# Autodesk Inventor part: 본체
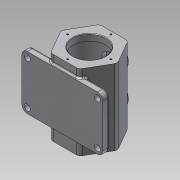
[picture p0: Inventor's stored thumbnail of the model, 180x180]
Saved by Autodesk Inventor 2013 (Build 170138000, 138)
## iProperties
Created: 2021-06
Part Number: 본체
Material: 알루미늄 6061
Document SubType Name: Modeling
Designer: Administrator
Mass: 1500.81 g
Surface Area: 1102.36 cm^2
Volume: 553.806 cm^3
Density: 2.71 g/cm^3
Author: Administrator
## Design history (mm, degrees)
sketch "스케치1" dims "d0" = 105
  geometry: L1 (-52.5, 0)-(-26.25, 45.466); L2 (-26.25, 45.466)-(26.25, 45.466); L3 (26.25, 45.466)-(52.5, 0); L4 (52.5, 0)-(26.25, -45.466); L5 (26.25, -45.466)-(-26.25, -45.466); L6 (-26.25, -45.466)-(-52.5, 0); L7 (-73.5, 0)-(73.5, 0) reference; L8 (0, -73.5)-(0, 73.5) reference; 3 further points
  constraints: 12 end point, 2 coincident, 1 horizontal alignment, 15 other
  dimensions: "d2" = 30 deg angle of L8 L3
extrude "돌출1" new body sketch "스케치1" stored distance "d4" = 140; taper "d5" = 0 deg
sketch "스케치2"
  geometry: C1 r 30 at (0, 0); 1 further point
  constraints: 1 centre point, 1 coincident
  dimensions: "d6" = 60 diameter of C1
extrude "돌출2" cut sketch "스케치2" distance "d8" = 12; taper "d9" = 0 deg
sketch "스케치3"
  geometry: C1 r 30 at (0, 0) reference; C2 r 37.5 at (0, 0)
  constraints: 1 centre point, 1 coincident
  dimensions: "d10" = 75 diameter of C2
extrude "돌출3" cut sketch "스케치3" distance "d12" = 116; taper "d13" = 0 deg
sketch "스케치4"
  geometry: C1 r 30 at (0, 0); 1 further point
  constraints: 1 centre point, 1 coincident
  dimensions: "d14" = 60 diameter of C1
extrude "돌출4" cut sketch "스케치4" distance "d16" = 12; taper "d17" = 0 deg
node "작업 평면1"
sketch "스케치5"
  geometry: L1 (-26.25, 70)-(26.25, 70) reference; C1 r 20 at (0, 30); C2 r 20 at (0, -30); 1 further point
  constraints: 2 centre point, 2 vertical alignment
  dimensions: "d19" = 40 distance from line of L1 C1.centre; "d20" = 60 distance of C2.centre C1.centre; "d21" = 40 diameter of C1; "d22" = 40 diameter of C2
extrude "돌출5" join sketch "스케치5" stored distance "d23" = 8; taper "d24" = 0 deg
sketch "스케치6"
  geometry: C1 r 20 at (0, 0) reference; C2 r 20 at (0, 60) reference; C3 r 15 at (0, 0); C4 r 15 at (0, 60); 1 further point
  constraints: 2 centre point, 2 coincident
  dimensions: "d25" = 30 diameter of C3; "d27" = 30 diameter of C4
extrude "돌출6" cut sketch "스케치6" distance "d28" = 8; taper "d29" = 0 deg
sketch "스케치7"
  geometry: C1 r 15 at (0, 0) reference; C2 r 15 at (0, -60) reference; C3 r 12.5 at (0, 0); C4 r 12.5 at (0, -60); 1 further point
  constraints: 2 centre point, 2 coincident
  dimensions: "d30" = 25 diameter of C3; "d32" = 25 diameter of C4
extrude "돌출7" cut sketch "스케치7" distance "d33" = 20; taper "d34" = 0 deg
sketch "스케치8"
  geometry: C1 r 30 at (0, 0) reference; 1 further point
  constraints: 1 vertical alignment
  dimensions: "d35" = 40 distance of point (0, 40) C1.centre
hole "구멍1" sketch "스케치8" at (0, 40) diameter "d36" = 3.242; stored, may be unused: countersink angle "d40" = 90 deg, drill point angle "d42" = 118 deg; dims "d37" = 8, "d38" = 30, "d39" = 8, "d41" = 10
sketch "스케치9"
  geometry: L1 (0, 0)-(28.284, 28.284); L2 (73.5, 0)-(-73.5, 0) reference; C1 r 30 at (0, 0) reference; 1 further point
  constraints: 2 end point, 1 coincident
  dimensions: "d46" = 40 distance of L1.start L1.end; "d47" = 45 deg angle of L2 L1
hole "구멍2" sketch "스케치9" at (28.284, 28.284) diameter "d48" = 3.242; stored, may be unused: countersink angle "d52" = 90 deg, drill point angle "d54" = 118 deg; dims "d49" = 8, "d50" = 30, "d51" = 8, "d53" = 10
node "작업 평면2"
sketch "스케치10"
  geometry: L1 (-75, 55)-(75, 55); L2 (75, 55)-(75, -45); L3 (75, -45)-(-75, -45); L4 (-75, -45)-(-75, 55); L5 (128.2, 0)-(-139.2, 0) reference; L6 (0, -98)-(0, 98) reference; L7 (52.5, -70)-(26.25, -70) reference; 1 further point
  constraints: 8 end point, 2 parallel, 1 horizontal, 1 perpendicular, 1 other
  dimensions: "d59" = 150 distance between parallel lines of L4 L2; "d61" = 25 distance between parallel lines of L7 L3; "d62" = 100 distance between parallel lines of L3 L1
extrude "돌출8" join sketch "스케치10" distance "d63" = 12; taper "d64" = 0 deg
fillet "모깎기1" dims "d65" = 10
sketch "스케치11"
  geometry: C1 r 5.5 at (-65, 35); C2 r 5.5 at (-65, -45); C3 r 5.5 at (65, -45); C4 r 5.5 at (65, 35); A1 r 10 centre (-65, -45) between (-75, -45) and (-65, -55) reference; A2 r 10 centre (-65, 35) between (-65, 45) and (-75, 35) reference; A3 r 10 centre (65, 35) between (75, 35) and (65, 45) reference; A4 r 10 centre (65, -45) between (65, -55) and (75, -45) reference; 1 further point
  constraints: 4 centre point, 4 coincident
  dimensions: "d66" = 11 diameter of C1; "d68" = 11 diameter of C2; "d69" = 11 diameter of C3; "d70" = 11 diameter of C4
extrude "돌출9" cut sketch "스케치11" distance "d71" = 12; taper "d72" = 0 deg
sketch "스케치12"
  geometry: L1 (75, -45)-(75, 35) reference; L2 (30.561, -55)-(65, -55) reference; 2 further points
  constraints: 1 other
  dimensions: "d73" = 14 distance from line of L1 point (61, -5); "d74" = 50 distance from line of L2 point (61, -5)
feature "엠보싱1" sketch "스케치12" dims "d75" = 0.5, "d76" = 0
fillet "모깎기2" dims "d77" = 8
fillet "모깎기3" dims "d78" = 5
fillet "모깎기4" dims "d79" = 3
chamfer "모따기1" distance "d80" = 1; stored, may be unused: second distance "d81" = 2, angle "d82" = 45 deg
fillet "모깎기5" dims "d83" = 3
node "솔리드1"
pattern_circular "원형 패턴1" dims angle "d44" = 360 deg
pattern_circular "원형 패턴2" dims angle "d56" = 360 deg
other parameters: "d18" = 52.5
